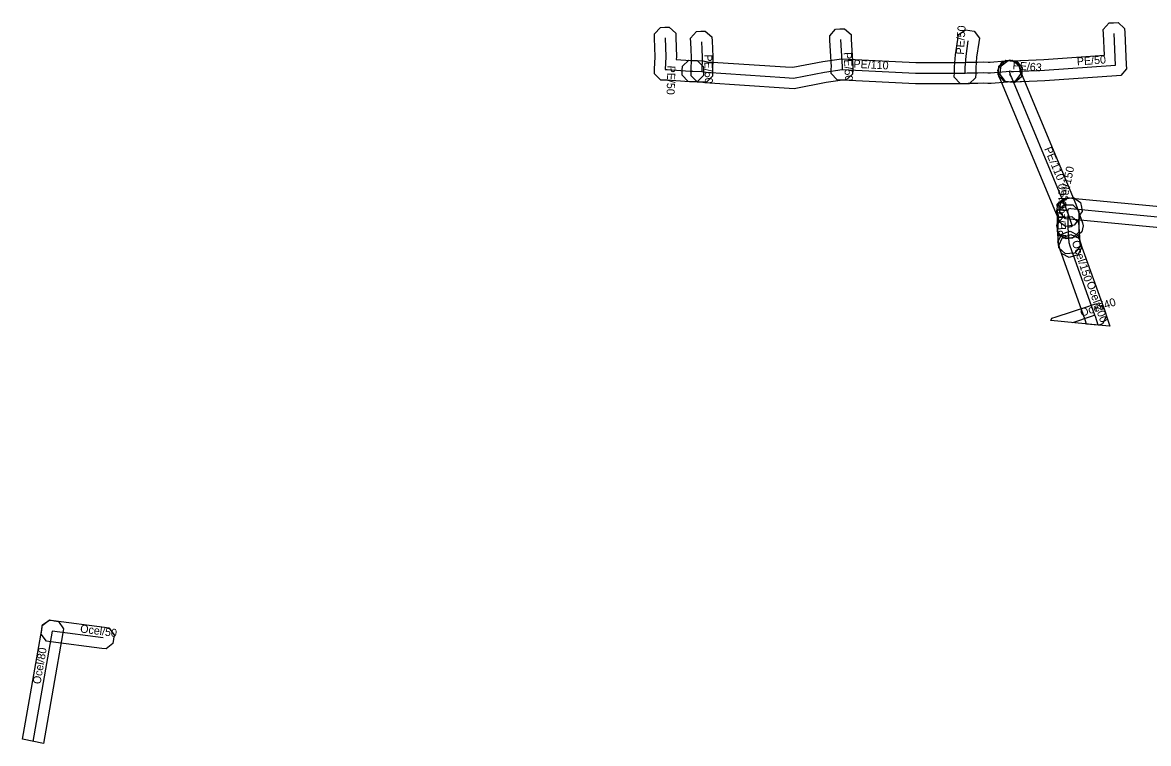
# Model space of a CAD drawing. Extents: x -444493 to -444287, y -1121040 to -1120972.
# Drawn here: x -444492.7 to -444387.2, y -1121040 to -1120972.4 of the extents above; entities that cross this region are included whole.
import ezdxf

# ---------------------------------------------------------------- set-up
doc = ezdxf.new("R2010")
doc.units = 0
for name, color, linetype in [('1', 7, 'Continuous'), ('14', 7, 'Continuous'), ('20', 7, 'Continuous')]:
    doc.layers.add(name, color=color, linetype=linetype)

msp = doc.modelspace()

# ---------------------------------------------------------------- linework, layer by layer
at = {"layer": '1'}
for points in [[(-444431.47, -1120975.66), (-444431.48, -1120975.91), (-444430.16, -1120976), (-444430.05, -1120976), (-444430, -1120976), (-444429.92, -1120976), (-444429.51, -1120976), (-444428.92, -1120976.59), (-444428.92, -1120977), (-444428.92, -1120977.41), (-444429.51, -1120978), (-444429.92, -1120978), (-444430, -1120978), (-444430.05, -1120978), (-444430.23, -1120978), (-444432.36, -1120977.85), (-444432.51, -1120977.85), (-444432.93, -1120977.85), (-444433.23, -1120977.54), (-444433.52, -1120977.24), (-444433.51, -1120976.82), (-444433.47, -1120975.66), (-444433.52, -1120973.92), (-444433.53, -1120973.5), (-444432.96, -1120972.9), (-444432.55, -1120972.89), (-444432.13, -1120972.88), (-444431.53, -1120973.45), (-444431.52, -1120973.86)], [(-444400.38, -1120975.99), (-444400.04, -1120976.03), (-444399.92, -1120976.02), (-444399.3, -1120976), (-444399.18, -1120976), (-444397.05, -1120975.91), (-444391.35, -1120975.5), (-444391.45, -1120973.51), (-444391.47, -1120973.09), (-444390.91, -1120972.48), (-444390.5, -1120972.46), (-444390.08, -1120972.44), (-444389.47, -1120973), (-444389.45, -1120973.41), (-444389.31, -1120976.38), (-444389.29, -1120976.79), (-444389.83, -1120977.4), (-444390.24, -1120977.43), (-444396.93, -1120977.91), (-444399.14, -1120978), (-444399.26, -1120978), (-444399.84, -1120978.02), (-444400.12, -1120978.03), (-444400.22, -1120978.02), (-444400.63, -1120977.97), (-444401.14, -1120977.31), (-444401.09, -1120976.9), (-444401.04, -1120976.49)], [(-444428.15, -1120973.79), (-444428.12, -1120974.2), (-444428.08, -1120974.89), (-444428.06, -1120975.7), (-444428.07, -1120977.05), (-444428.07, -1120977.46), (-444428.66, -1120978.04), (-444429.08, -1120978.04), (-444429.49, -1120978.04), (-444430.07, -1120977.45), (-444430.07, -1120977.03), (-444430.06, -1120975.72), (-444430.08, -1120974.97), (-444430.12, -1120974.32), (-444430.14, -1120973.91), (-444429.59, -1120973.29), (-444429.18, -1120973.26), (-444428.77, -1120973.24)], [(-444415.1, -1120973.58), (-444415.08, -1120973.99), (-444415.05, -1120974.52), (-444414.94, -1120976.58), (-444414.95, -1120976.88), (-444414.97, -1120977.29), (-444415.58, -1120977.86), (-444415.99, -1120977.84), (-444416.4, -1120977.82), (-444416.97, -1120977.21), (-444416.95, -1120976.8), (-444416.94, -1120976.6), (-444417.05, -1120974.64), (-444417.08, -1120974.11), (-444417.1, -1120973.69), (-444416.55, -1120973.07), (-444416.14, -1120973.05), (-444415.72, -1120973.03)], [(-444405.43, -1120977.56), (-444405.42, -1120977.14), (-444405.4, -1120976.6), (-444405.33, -1120975.48), (-444405.11, -1120974.02), (-444405.05, -1120973.61), (-444404.38, -1120973.12), (-444403.97, -1120973.18), (-444403.56, -1120973.24), (-444403.07, -1120973.91), (-444403.13, -1120974.32), (-444403.34, -1120975.7), (-444403.4, -1120976.7), (-444403.42, -1120977.22), (-444403.44, -1120977.63), (-444404.04, -1120978.2), (-444404.46, -1120978.18), (-444404.87, -1120978.16)], [(-444430.29, -1120975.98), (-444429.87, -1120976), (-444428.96, -1120976.04), (-444428.56, -1120976.12), (-444421.23, -1120976.6), (-444420.56, -1120976.64), (-444417.76, -1120976.11), (-444416, -1120975.84), (-444409.03, -1120976.19), (-444404.49, -1120976.18), (-444404.28, -1120976.15), (-444403.25, -1120976.16), (-444402.68, -1120976.13), (-444402.24, -1120976.17), (-444402.08, -1120976.16), (-444400.67, -1120976.05), (-444400.42, -1120976.02), (-444400.01, -1120975.96), (-444399.35, -1120976.46), (-444399.29, -1120976.87), (-444399.23, -1120977.28), (-444399.73, -1120977.94), (-444400.14, -1120978), (-444400.45, -1120978.04), (-444401.96, -1120978.16), (-444402.3, -1120978.17), (-444402.72, -1120978.13), (-444403.21, -1120978.16), (-444404.14, -1120978.15), (-444404.35, -1120978.18), (-444409.07, -1120978.19), (-444415.9, -1120977.84), (-444417.42, -1120978.08), (-444420.44, -1120978.66), (-444421.37, -1120978.59), (-444428.8, -1120978.1), (-444429.18, -1120978.04), (-444429.97, -1120978), (-444430.38, -1120977.98), (-444430.94, -1120977.37), (-444430.92, -1120976.95), (-444430.9, -1120976.54)], [(-444401.24, -1120977.51), (-444401.24, -1120977.29), (-444401.36, -1120976.93), (-444400.99, -1120976.19), (-444400.6, -1120976.06), (-444400.2, -1120975.93), (-444399.46, -1120976.3), (-444399.33, -1120976.69), (-444399.33, -1120976.71), (-444399.24, -1120976.98), (-444399.19, -1120977.16), (-444399.17, -1120977.2), (-444394.04, -1120989.48), (-444393.9, -1120989.83), (-444393.81, -1120990.1), (-444393.43, -1120991.21), (-444393.34, -1120991.49), (-444393.49, -1120992.08), (-444393.72, -1120992.28), (-444394.01, -1120992.53), (-444394.56, -1120992.65), (-444394.96, -1120992.73), (-444395.66, -1120992.28), (-444395.74, -1120991.87), (-444395.82, -1120991.47), (-444395.58, -1120991.1), (-444395.7, -1120990.75), (-444395.78, -1120990.53), (-444395.9, -1120990.24), (-444400.99, -1120978.02), (-444401.14, -1120977.72)], [(-444399.77, -1120978.06), (-444400.18, -1120978.03), (-444400.36, -1120978.01), (-444400.77, -1120977.98), (-444401.31, -1120977.34), (-444401.28, -1120976.93), (-444401.24, -1120976.52), (-444400.61, -1120975.98), (-444400.2, -1120976.02), (-444400.01, -1120976.03), (-444399.6, -1120976.06), (-444399.07, -1120976.7), (-444399.1, -1120977.11), (-444399.13, -1120977.52)], [(-444393.46, -1120990.15), (-444393.74, -1120990.53), (-444393.7, -1120990.78), (-444394.19, -1120991.45), (-444394.6, -1120991.51), (-444395.01, -1120991.57), (-444395.68, -1120991.08), (-444395.74, -1120990.67), (-444395.83, -1120990.09), (-444395.75, -1120989.72), (-444395.68, -1120989.42), (-444395.23, -1120988.99), (-444394.92, -1120988.94), (-444394.66, -1120988.9), (-444394.25, -1120988.84), (-444393.59, -1120989.33), (-444393.52, -1120989.74)], [(-444395.76, -1120992.07), (-444395.76, -1120991.66), (-444395.75, -1120990.51), (-444395.75, -1120990.1), (-444395.16, -1120989.52), (-444394.74, -1120989.52), (-444394.33, -1120989.52), (-444393.75, -1120990.11), (-444393.75, -1120990.53), (-444393.76, -1120991.68), (-444393.76, -1120992.09), (-444394.35, -1120992.67), (-444394.77, -1120992.67), (-444395.18, -1120992.67)], [(-444395.63, -1120993.57), (-444395.66, -1120993.16), (-444395.76, -1120991.74), (-444395.79, -1120991.33), (-444395.24, -1120990.7), (-444394.83, -1120990.67), (-444394.42, -1120990.64), (-444393.79, -1120991.19), (-444393.76, -1120991.6), (-444393.66, -1120993.02), (-444393.63, -1120993.43), (-444394.18, -1120994.06), (-444394.59, -1120994.09), (-444395, -1120994.12)], [(-444395.39, -1120994.1), (-444395.51, -1120993.71), (-444395.61, -1120993.4), (-444395.74, -1120993), (-444395.36, -1120992.27), (-444394.97, -1120992.14), (-444394.57, -1120992.01), (-444393.84, -1120992.39), (-444393.71, -1120992.78), (-444393.61, -1120993.09), (-444393.48, -1120993.49), (-444393.86, -1120994.23), (-444394.25, -1120994.35), (-444394.65, -1120994.48)], [(-444390.85, -1121000.92), (-444393.03, -1121000.71), (-444393.16, -1121000.32), (-444393.19, -1121000.21), (-444395.5, -1120993.74), (-444395.64, -1120993.35), (-444395.29, -1120992.6), (-444394.9, -1120992.46), (-444394.51, -1120992.32), (-444393.76, -1120992.67), (-444393.62, -1120993.06), (-444391.3, -1120999.56), (-444391.26, -1120999.68)], [(-444391.89, -1121000.82), (-444396.39, -1121000.39), (-444396.28, -1121000.17), (-444395.89, -1121000.04), (-444392.92, -1120999.05), (-444392.56, -1120998.93), (-444392.17, -1120998.8), (-444391.43, -1120999.18), (-444391.3, -1120999.57), (-444391.17, -1120999.96), (-444391.54, -1121000.7)], [(-444490.78, -1121040.03), (-444492.74, -1121039.62), (-444490.94, -1121029.33), (-444490.86, -1121028.92), (-444490.19, -1121028.45), (-444489.78, -1121028.52), (-444489.37, -1121028.59), (-444488.9, -1121029.27), (-444488.97, -1121029.67)], [(-444484.91, -1121031.17), (-444485.32, -1121031.12), (-444490.08, -1121030.49), (-444490.49, -1121030.44), (-444491, -1121029.78), (-444490.94, -1121029.37), (-444490.89, -1121028.96), (-444490.23, -1121028.46), (-444489.82, -1121028.51), (-444485.06, -1121029.14), (-444484.65, -1121029.19), (-444484.15, -1121029.85), (-444484.2, -1121030.26), (-444484.26, -1121030.67)]]:
    msp.add_lwpolyline(points, close=True, dxfattribs=at)
msp.add_lwpolyline([(-444375.1, -1120992.75), (-444394.6, -1120990.89), (-444395.02, -1120990.85), (-444395.54, -1120990.21), (-444395.51, -1120989.79), (-444395.47, -1120989.38), (-444394.83, -1120988.85), (-444394.42, -1120988.9), (-444374.91, -1120990.76)], dxfattribs=at)
at = {"layer": '14'}
for points in [[(-444432.52, -1120973.89), (-444432.47, -1120975.66), (-444432.51, -1120976.85), (-444432.33, -1120976.85), (-444430.19, -1120977), (-444430.05, -1120977), (-444430, -1120977), (-444429.92, -1120977)], [(-444416.08, -1120974.05), (-444416.05, -1120974.58), (-444415.94, -1120976.59), (-444415.95, -1120976.84)], [(-444400.1, -1120977.03), (-444400.08, -1120977.03), (-444399.88, -1120977.02), (-444399.28, -1120977), (-444399.16, -1120977), (-444396.99, -1120976.91), (-444390.31, -1120976.43), (-444390.45, -1120973.46)], [(-444429.12, -1120974.26), (-444429.08, -1120974.93), (-444429.06, -1120975.71), (-444429.07, -1120977.04)], [(-444404.42, -1120977.18), (-444404.4, -1120976.65), (-444404.33, -1120975.59), (-444404.12, -1120974.17)], [(-444429.92, -1120977), (-444429.07, -1120977.04), (-444428.68, -1120977.11), (-444421.3, -1120977.6), (-444420.5, -1120977.65), (-444417.59, -1120977.1), (-444415.95, -1120976.84), (-444409.05, -1120977.19), (-444404.42, -1120977.18), (-444404.21, -1120977.15), (-444403.23, -1120977.16), (-444402.7, -1120977.13), (-444402.27, -1120977.17), (-444402.02, -1120977.16), (-444400.56, -1120977.05), (-444400.28, -1120977.01)], [(-444400.1, -1120977.03), (-444400.28, -1120977.01)], [(-444400.28, -1120977.01), (-444400.28, -1120977.01), (-444400.2, -1120977.27), (-444400.24, -1120977.28), (-444400.08, -1120977.61), (-444394.97, -1120989.86), (-444394.84, -1120990.18), (-444394.76, -1120990.42), (-444394.38, -1120991.53), (-444394.47, -1120991.61), (-444394.76, -1120991.67)], [(-444394.51, -1120989.89), (-444394.77, -1120989.93), (-444394.81, -1120990.12), (-444394.75, -1120990.52)], [(-444394.51, -1120989.89), (-444375, -1120991.75), (-444353.03, -1120993.85), (-444349.44, -1120994.19), (-444341.52, -1120994.95), (-444333.6, -1121000), (-444329.06, -1121002.89), (-444328.17, -1121003.89), (-444327.84, -1121004.06)], [(-444394.76, -1120991.67), (-444394.75, -1120990.52)], [(-444394.66, -1120993.09), (-444394.76, -1120991.67)], [(-444394.56, -1120993.4), (-444394.66, -1120993.09)], [(-444391.94, -1121000.81), (-444392.21, -1121000), (-444392.25, -1120999.88), (-444394.56, -1120993.4)], [(-444392.25, -1120999.88), (-444392.6, -1121000), (-444394.36, -1121000.58)], [(-444489.95, -1121029.5), (-444491.76, -1121039.83)], [(-444485.19, -1121030.13), (-444489.95, -1121029.5)]]:
    msp.add_lwpolyline(points, dxfattribs=at)

# ---------------------------------------------------------------- texts
at = {"layer": '20'}
for s, rotation, p in [('PE/50', 86.2218, (-444404.54, -1120975.47)), ('PE/50', 271.4688, (-444428.86, -1120975.45)), ('PE/50', 273.1325, (-444415.8, -1120975.24)), ('PE/110', 357.0962, (-444414.89, -1120976.68)), ('PE/63', 355.3141, (-444399.99, -1120976.82)), ('PE/50', 4.11, (-444393.92, -1120976.47)), ('PE/50', 268.0748, (-444432.3, -1120976.47)), ('PE/110', 292.6431, (-444397.02, -1120984.28)), ('Ocel/150', 78.1113, (-444395.01, -1120989.94)), ('PE/160', 89.5018, (-444394.95, -1120990.85)), ('PE/160', 94.0283, (-444394.91, -1120992.53)), ('Ocel/150', 287.8787, (-444394.43, -1120993)), ('Ocel/200', 289.6275, (-444393.06, -1120996.86)), ('Ocel/40', 18.3539, (-444393.5, -1121000.03)), ('Ocel/50', 352.4827, (-444487.37, -1121029.61)), ('Ocel/80', 80.0714, (-444491.06, -1121034.51))]:
    msp.add_text(s, height=0.75, rotation=rotation, dxfattribs=at).set_placement(p)

doc.saveas('drawing.dxf')
